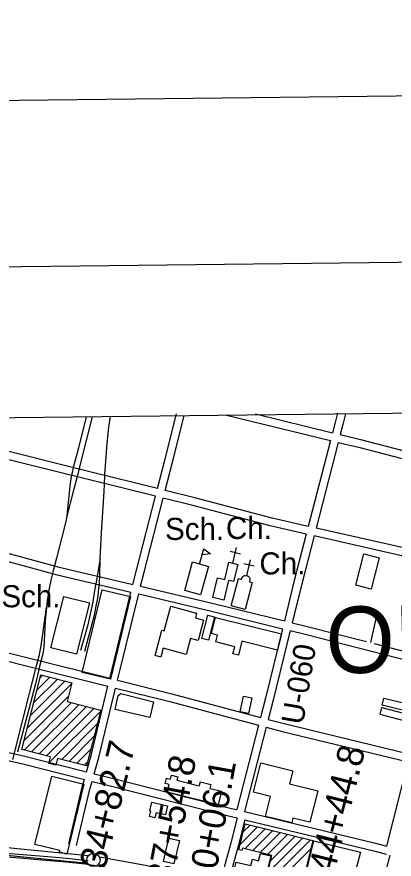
# Model space of a CAD drawing. Extents: x 3677843 to 3715951, y 511991 to 537744.
# Drawn here: x 3687695 to 3689113, y 533993 to 537161 of the extents above; entities that cross this region are included whole.
import ezdxf

# ---------------------------------------------------------------- set-up
doc = ezdxf.new("R2010")
doc.units = 0
for name, color, linetype in [('G-ANNO-NPLT', 7, 'Continuous'), ('V-ANNO-SYMB', 7, 'Continuous'), ('V-BLDG-IDEN', 7, 'Continuous'), ('V-BLDG-OTLN', 7, 'Continuous'), ('V-GRID-FRAM', 7, 'Continuous'), ('V-RAIL-TRAK', 7, 'Continuous'), ('V-RIVR-RANG-IDEN', 7, 'Continuous'), ('V-ROAD-CNTR', 7, 'Continuous'), ('V-SITE-OTLN', 7, 'Continuous'), ('V-SITE-OTLN-IDEN', 7, 'Continuous'), ('V-SURV-IDEN', 7, 'Continuous'), ('V-SURV-LINE', 7, 'Continuous'), ('V-TOPO-GNAM-IDEN', 7, 'Continuous')]:
    doc.layers.add(name, color=color, linetype=linetype)

msp = doc.modelspace()

# ---------------------------------------------------------------- linework, layer by layer
at = {"layer": 'G-ANNO-NPLT'}
msp.add_lwpolyline([(3678703.9, 512574.2), (3715368.2, 512995.5), (3715090.5, 537160.6), (3678426.3, 536739.3)], close=True, dxfattribs=at)
at = {"layer": 'V-ANNO-SYMB'}
msp.add_lwpolyline([(3681446.7, 513230.8), (3714527.7, 513611), (3714264.4, 536526), (3681183.4, 536145.9), (3681446.7, 513230.8)], dxfattribs=at)
at = {"layer": 'V-BLDG-OTLN'}
for p, q in [((3688381.7, 535102.3), (3688397.2, 535160.3)), ((3687781.8, 534675.7), (3687790.8, 534684.7)), ((3687733.1, 534485.6), (3687900.8, 534653.3)), ((3687745.3, 534533.1), (3687875.3, 534663.1)), ((3687757.5, 534580.6), (3687847.1, 534670.3)), ((3687769.6, 534628.1), (3687819, 534677.5)), ((3687721, 534438.1), (3687888.6, 534605.7)), ((3687721.7, 534403.5), (3687900.4, 534582.1)), ((3687749.9, 534396.3), (3687928.5, 534574.9)), ((3687778, 534389.1), (3687956.7, 534567.7)), ((3687806.2, 534381.8), (3687984.8, 534560.5)), ((3687815.8, 534356.1), (3688008.8, 534549.1)), ((3687863.2, 534368.1), (3687996.6, 534501.6)), ((3687891.3, 534360.9), (3687984.5, 534454.1)), ((3687919.5, 534353.7), (3687972.3, 534406.6)), ((3687947.6, 534346.5), (3687960.2, 534359.1)), ((3688533.9, 534048.9), (3688599.6, 534114.6)), ((3688545.4, 534095.8), (3688571.2, 534121.6)), ((3688552.2, 534031.8), (3688628, 534107.7)), ((3688580.5, 534024.9), (3688656.4, 534100.7)), ((3688608.9, 534017.9), (3688684.8, 534093.7)), ((3688637.3, 534010.9), (3688713.2, 534086.8)), ((3688626.2, 533893.8), (3688798.3, 534065.9)), ((3688637.4, 533940.3), (3688769.9, 534072.8)), ((3688648.5, 533986.8), (3688741.5, 534079.8)), ((3688653.7, 533885.9), (3688800.2, 534032.4))]:
    msp.add_line(p, q, dxfattribs=at)
for points in [[(3688397.2, 535160.3), (3688423.2, 535141.4), (3688391.2, 535138)], [(3688969.1, 535023.2), (3688999.2, 535140.8), (3689057, 535126), (3689027, 535008.4)], [(3688325.6, 535003.8), (3688355.6, 535110.8), (3688414.8, 535094.2), (3688384.9, 534987.2)], [(3688430.9, 534977), (3688448.4, 535051.1), (3688476.3, 535044.5), (3688491.7, 535109.4), (3688524.8, 535101.6), (3688509.4, 535036.7), (3688490.9, 535041.1), (3688473.3, 534966.9)], [(3688500.4, 534945.8), (3688527.8, 535048.5), (3688539.3, 535045.4), (3688539.5, 535047.2), (3688539.9, 535048.9), (3688540.6, 535050.6), (3688541.4, 535052.2), (3688542.3, 535053.7), (3688543.5, 535055.1), (3688544.8, 535056.3), (3688546.2, 535057.4), (3688547.8, 535058.3), (3688549.4, 535059.1), (3688551.1, 535059.6), (3688552.8, 535060), (3688554.6, 535060.1), (3688556.4, 535060.1), (3688558.2, 535059.8), (3688559.9, 535059.4), (3688561.6, 535058.7), (3688563.2, 535057.9), (3688564.7, 535056.9), (3688566, 535055.7), (3688567.3, 535054.4), (3688568.3, 535053), (3688569.2, 535051.4), (3688570, 535049.8), (3688570.5, 535048.1), (3688570.8, 535046.3), (3688571, 535044.5), (3688570.9, 535042.8), (3688570.6, 535041), (3688570.2, 535039.3), (3688569.5, 535037.6), (3688568.7, 535036), (3688579.5, 535033.4), (3688552.4, 534931.9)], [(3687940.2, 534695.7), (3688015.8, 535006.4), (3688121.8, 534980.7), (3688046.2, 534669.9)], [(3687822.6, 534788.2), (3687871.6, 534981.3), (3687968.2, 534956.8), (3687919.2, 534763.7)], [(3688396.4, 534892), (3688376.1, 534815.8), (3688347.6, 534823.4), (3688331.5, 534763.1), (3688244.4, 534786.2), (3688235.6, 534753), (3688214.6, 534758.6), (3688239.9, 534853.8), (3688248.9, 534851.3), (3688273.7, 534944.3), (3688370.6, 534918.5), (3688365.7, 534900.2)], [(3688390.3, 534823.5), (3688412.5, 534911.2), (3688437.3, 534904.9), (3688415, 534817.2)], [(3688441.8, 534902), (3688689.3, 534840), (3688674.1, 534779.3), (3688540.9, 534812.7), (3688527.7, 534759.9), (3688506.8, 534765.2), (3688513.6, 534792.2), (3688442.5, 534810), (3688448.9, 534835.5), (3688426.6, 534841.2)], [(3688010.1, 534554), (3687956.4, 534344.3), (3687847.6, 534372.1), (3687841.1, 534346.6), (3687815.1, 534353.2), (3687821.4, 534378), (3687712.7, 534405.8), (3687784.5, 534686.3), (3687901.6, 534656.4), (3687883.7, 534586.4)], [(3688194.8, 534525.6), (3688063.7, 534556.6), (3688076.1, 534608.9), (3688085.8, 534616), (3688208.8, 534585)], [(3688534.1, 534547.4), (3688546.4, 534606.6), (3688578.3, 534599.9), (3688566, 534540.8)], [(3689204.5, 534538.4), (3689067.9, 534571.7), (3689074.5, 534599), (3689211.2, 534565.8)], [(3689194, 534502.4), (3689060.1, 534537.7), (3689066.9, 534563.5), (3689200.8, 534528.2)], [(3688584.3, 534245.5), (3688611.7, 534355), (3688732.1, 534324.9), (3688719.9, 534276.1), (3688825.6, 534249.6), (3688796.1, 534131.9), (3688732.6, 534147.8), (3688727.9, 534129.2), (3688629.8, 534153.7), (3688648.7, 534229.4)], [(3687946.7, 534275.7), (3687882.2, 534012.6), (3687855.3, 534019.2), (3687856.8, 534025.3), (3687762.2, 534048.5), (3687826, 534305.3)], [(3688451.1, 534197.2), (3688260, 534245.6), (3688267.3, 534274.3), (3688252.4, 534278.1), (3688257.3, 534297.5), (3688272.6, 534293.6), (3688276.5, 534309.2), (3688299.8, 534303.3), (3688296.4, 534290.1), (3688380.6, 534268.8), (3688384.5, 534284.4), (3688424.2, 534274.4), (3688420.4, 534259.4), (3688464.1, 534248.3)], [(3688201.7, 534207.7), (3688260.9, 534194), (3688252.9, 534159.6), (3688217.9, 534167.7), (3688213.6, 534149.2), (3688193.9, 534153.8), (3688198.6, 534173.9), (3688194.2, 534175)], [(3688552.9, 534126.1), (3688807.8, 534063.5), (3688777.2, 533938.6), (3688762.2, 533942.2), (3688759.4, 533930.6), (3688774.1, 533926.9), (3688764.3, 533886.9), (3688750.1, 533890.3), (3688743.1, 533861.7), (3688626.1, 533893.4), (3688653.4, 534007), (3688543.1, 534034.1), (3688541, 534025.4), (3688528.9, 534028.3)], [(3688305.6, 534063.6), (3688285.4, 533975.2), (3688246.1, 533984.2), (3688266.2, 534072.5)], [(3688780.7, 533938.4), (3688810.7, 534062.1), (3688987, 534019.4), (3688953.6, 533896.3)], [(3688649.3, 534005.6), (3688620.6, 533888.6), (3688502.8, 533914.6), (3688519.5, 533982.5), (3688574.3, 533969.1), (3688580.2, 533993), (3688603.7, 533987.3), (3688610.5, 534015.1)]]:
    msp.add_lwpolyline(points, close=True, dxfattribs=at)
at = {"layer": 'V-GRID-FRAM'}
msp.add_lwpolyline([(3681899.6, 535587.1), (3713561.2, 535950.9), (3713778.1, 517769.3), (3682100.6, 517405.3), (3681899.6, 535587.1)], dxfattribs=at)
at = {"layer": 'V-RAIL-TRAK'}
for points in [[(3687955.4, 535656.7), (3687924.6, 535534.6), (3687905.4, 535460.4), (3687903.2, 535451.2), (3687901.1, 535442), (3687899.7, 535434.9), (3687899.3, 535432.7), (3687897.7, 535423.4), (3687896.4, 535414), (3687895.3, 535404.6), (3687894.4, 535395.2), (3687881.2, 535272.4), (3687843.6, 535124.8), (3687831.7, 535077.8), (3687823.9, 535047.1), (3687814.7, 535004.6), (3687808.2, 534964.1), (3687805.7, 534939.2), (3687800.7, 534890), (3687799.6, 534863.3), (3687797.4, 534814.6), (3687796.2, 534790.6), (3687791.7, 534765.9), (3687780.2, 534717.8), (3687764.7, 534652.6), (3687697.4, 534395)], [(3687881.2, 535272.4), (3687910.3, 535385.8), (3687921.1, 535428.9), (3687957.1, 535572.6), (3687979, 535657)], [(3687949.9, 534775.6), (3687986.9, 534910.3), (3687992.1, 534938.4), (3687999.3, 534974.8), (3688004.3, 535021.4), (3688005, 535032.3), (3688006.7, 535059.8), (3688008.2, 535124.2), (3688013.3, 535222.2), (3688020.4, 535335.3), (3688022.7, 535376.5), (3688023.8, 535402.1), (3688025.5, 535440.2), (3688034.6, 535556.8), (3688040.9, 535617.8), (3688046.3, 535657.7)], [(3688008.2, 535124.2), (3687992.5, 535035.3), (3687986.8, 535003.4), (3687980.4, 534960.8), (3687961.4, 534874.3), (3687933.5, 534778.1)], [(3687679.1, 534368.1), (3687716.7, 534517.2), (3687769, 534720.5), (3687779.4, 534762.4), (3687784.6, 534789.2), (3687790.4, 534831), (3687805.7, 534939.2)], [(3687136, 534007.2), (3687280.5, 534011.4), (3687352.4, 534012.8), (3687366.1, 534013.5), (3687405.3, 534015.6), (3687447.6, 534017.8), (3687503.1, 534021.1), (3687546.9, 534022.9), (3687599, 534020), (3687701.8, 534011.4), (3687826.6, 534002.4), (3687881.5, 533997.4), (3687962.4, 533988.7)], [(3687405.3, 534015.6), (3687534.1, 534011.4), (3687595.2, 534006.5), (3687705.6, 533998), (3687788.5, 533990.6), (3687866.7, 533983.8), (3687916.7, 533979.5), (3687951, 533975.1), (3687998.4, 533968), (3688073.2, 533955), (3688174.1, 533937.5), (3688336.7, 533909), (3688471.6, 533885.9), (3688603.1, 533863.5)]]:
    msp.add_lwpolyline(points, dxfattribs=at)
at = {"layer": 'V-ROAD-CNTR'}
msp.add_line((3689044.9, 534902.7), (3689023.7, 534807.4), dxfattribs=at)
for points in [[(3688223.5, 535386.6), (3688251.1, 535493.1), (3688295, 535667.7)], [(3688591.6, 535667.6), (3688881.6, 535596.7)], [(3688900.3, 535670.2), (3688891.4, 535634.7), (3688881.6, 535596.7)], [(3688930.6, 535667.3), (3688920.5, 535627.3), (3688910.7, 535589.5)], [(3688252.6, 535379.3), (3688280.2, 535485.7), (3688324.1, 535660.4)], [(3688478.1, 535664.5), (3688874.1, 535567.6)], [(3688910.7, 535589.5), (3688986.3, 535571), (3689435.2, 535454.3)], [(3688223.5, 535386.6), (3687969.5, 535450.2), (3687583.2, 535545.9), (3687532.8, 535557.5)], [(3688874.1, 535567.6), (3688790.4, 535244.7)], [(3688903.2, 535560.5), (3688819.7, 535238)], [(3688903.2, 535560.5), (3688979, 535541.9), (3689427.7, 535425.3)], [(3688216, 535357.6), (3687962.3, 535421.1), (3687576.2, 535516.7), (3687525.3, 535528.5)], [(3688130.8, 535026.4), (3688144, 535080), (3688216, 535357.6)], [(3688160, 535019.6), (3688173.1, 535072.7), (3688245.1, 535350.3)], [(3688782.9, 535215.6), (3688647.6, 535246.3), (3688355.9, 535322.5), (3688245.1, 535350.3)], [(3688790.4, 535244.7), (3688654.7, 535275.4), (3688363.4, 535351.6), (3688252.6, 535379.3)], [(3689348.1, 535107.3), (3689143.5, 535164.6), (3688819.7, 535238)], [(3687439.6, 535200.8), (3687530.3, 535179.1), (3687853.4, 535091.5), (3688120.2, 535028.9), (3688130.8, 535026.4)], [(3688782.9, 535215.6), (3688737.8, 535041.3), (3688700.5, 534889.1)], [(3688812.2, 535209), (3688766.8, 535034), (3688729.6, 534881.8)], [(3689341.1, 535078.1), (3689136.2, 535135.5), (3688812.2, 535209)], [(3687432, 535171.8), (3687522.9, 535150), (3687846.1, 535062.5), (3688113.3, 534999.7), (3688123.7, 534997.3)], [(3688160, 535019.6), (3688433.8, 534955.2), (3688700.5, 534889.1)], [(3688044.1, 534673.2), (3688051.4, 534703.2), (3688123.7, 534997.3)], [(3688073.2, 534665.9), (3688080.5, 534696.1), (3688152.9, 534990.4)], [(3688152.9, 534990.4), (3688426.8, 534926), (3688693.4, 534859.9)], [(3688729.6, 534881.8), (3688786.4, 534867.8), (3689009.4, 534811.1)], [(3687348.3, 534847.5), (3687370.5, 534842.1), (3687736.7, 534749.7), (3688044.1, 534673.2)], [(3688693.4, 534859.9), (3688629.5, 534598.9), (3688610.8, 534526.5)], [(3688722.5, 534852.7), (3688658.6, 534591.6), (3688639.8, 534518.8)], [(3688722.5, 534852.7), (3688779.1, 534838.7), (3689180.1, 534736.7), (3689255.3, 534717.8)], [(3687341, 534818.4), (3687363.2, 534813), (3687729.4, 534720.6), (3688037, 534644)], [(3689038.2, 534803.7), (3689187.4, 534765.8), (3689262.3, 534747)], [(3688073.2, 534665.9), (3688276.9, 534615.2), (3688610.8, 534526.5)], [(3687956.6, 534321.9), (3687973.5, 534383.1), (3688037, 534644)], [(3687985.7, 534314.6), (3688002.5, 534375.6), (3688066.1, 534636.8)], [(3688066.1, 534636.8), (3688269.4, 534586.1), (3688603.4, 534497.4)], [(3688603.4, 534497.4), (3688521.7, 534179.6)], [(3688639.8, 534518.8), (3688699.5, 534502.9), (3689172.8, 534387.9)], [(3687258.8, 534488.4), (3687297.2, 534478.9), (3687724.1, 534380.3), (3687956.6, 534321.9)], [(3688632.4, 534489.7), (3688550.8, 534172.5)], [(3688632.4, 534489.7), (3688692.1, 534473.8), (3689165.5, 534358.8)], [(3687251.6, 534459.3), (3687290.2, 534449.7), (3687717.1, 534351.1), (3687948.7, 534293)], [(3689085.5, 534042.7), (3689165.5, 534358.8)], [(3687985.7, 534314.6), (3688047.7, 534299.1), (3688502.2, 534184.3), (3688521.7, 534179.6)], [(3687890.1, 534051), (3687940.6, 534263.6), (3687948.7, 534293)], [(3687919.2, 534044), (3687969.6, 534256.2), (3687977.8, 534285.7)], [(3687977.8, 534285.7), (3688040.4, 534270), (3688495, 534155.2), (3688522.6, 534148.5)], [(3688522.8, 534149), (3688497.8, 534049.6), (3688476.6, 533971.3), (3688459.4, 533901.8)], [(3688550.8, 534172.5), (3689048.6, 534052), (3689085.5, 534042.7)], [(3688551.9, 534141.6), (3688526.8, 534042.1), (3688505.7, 533963.8), (3688488.6, 533894.6)], [(3688551.9, 534141.4), (3689041.4, 534022.8), (3689083.6, 534012.3)], [(3689054.2, 533834), (3689098.5, 534008.5)]]:
    msp.add_lwpolyline(points, dxfattribs=at)
at = {"layer": 'V-SITE-OTLN'}
for p, q in [((3688506.6, 535106.2), (3688520, 535164.7)), ((3688535, 535140.7), (3688496, 535149.6)), ((3688587.4, 535094.5), (3688548.5, 535103.7)), ((3688558.7, 535060.2), (3688572.6, 535118.6))]:
    msp.add_line(p, q, dxfattribs=at)
at = {"layer": 'V-SURV-LINE'}
for points in [[(3687454.5, 534057), (3687964.1, 534007)], [(3687961.1, 533977.1), (3687451.6, 534027.2)], [(3688004.8, 534001.4), (3688233.4, 533960.8)]]:
    msp.add_lwpolyline(points, dxfattribs=at)
msp.add_circle((3687982.5, 533990.1), 25, dxfattribs=at)

# ---------------------------------------------------------------- texts
at = {"layer": 'V-BLDG-IDEN'}
for p in [(3688251.9, 535193.6), (3687636.6, 534940.4)]:
    msp.add_text('Sch.', height=83, dxfattribs=at).set_placement(p)
at = {"layer": 'V-RIVR-RANG-IDEN'}
msp.add_text('U-060', height=83, rotation=80.5023, dxfattribs=at).set_placement((3688770.4, 534496))
at = {"layer": 'V-SITE-OTLN-IDEN'}
for p in [(3688480.7, 535197.1), (3688606.6, 535063.9)]:
    msp.add_text('Ch.', height=83, dxfattribs=at).set_placement(p)
at = {"layer": 'V-SURV-IDEN'}
for s, rotation, p in [('   534+82.7   ', 76.3393, (3687981.9, 533769.5)), ('   544+44.8   ', 75.8993, (3688841.9, 533754.2)), ('   537+54.8   ', 79.3194, (3688245.3, 533712)), ('   540+06.1   ', 79.7764, (3688399.9, 533694.7)), ('   545+68.4   ', 75.9182, (3689141.9, 533578.9))]:
    msp.add_text(s, height=100, rotation=rotation, dxfattribs=at).set_placement(p)
at = {"layer": 'V-TOPO-GNAM-IDEN'}
msp.add_text('ORLEANS', height=250, rotation=1.3443, dxfattribs=at).set_placement((3688858.3, 534690.4))

doc.saveas('drawing.dxf')
